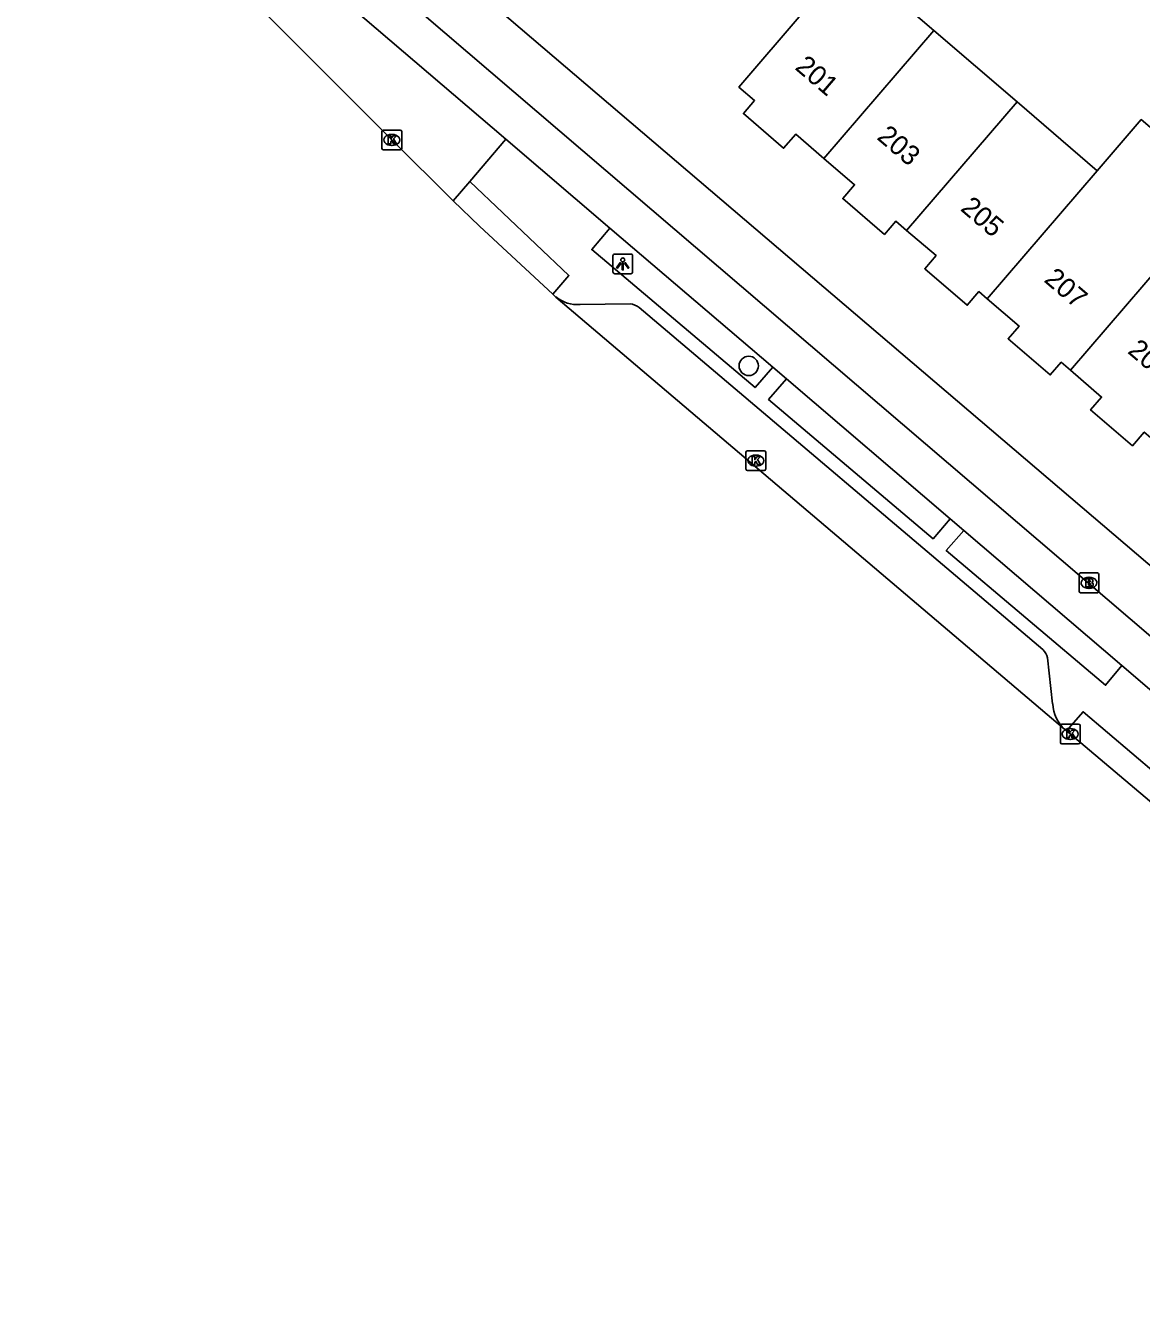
# Model space of a CAD drawing. Extents: x 162532 to 163264, y 381233 to 382042.
# Drawn here: x 162541.7 to 162598.2, y 381729.9 to 381794.9 of the extents above; entities that cross this region are included whole.
import ezdxf

# ---------------------------------------------------------------- set-up
doc = ezdxf.new("R2010")
doc.units = 0
for name, color, linetype in [('IMGEO_Berm_open', 7, 'Continuous'), ('IMGEO_Boom', 7, 'Continuous'), ('IMGEO_Brandkraan', 7, 'Continuous'), ('IMGEO_Fietspad_gesloten', 7, 'Continuous'), ('IMGEO_Kolk', 7, 'Continuous'), ('IMGEO_Lichtpunt', 7, 'Continuous'), ('IMGEO_Pand', 7, 'Continuous'), ('IMGEO_Pand_nummerreeks', 7, 'Continuous'), ('IMGEO_Parkeervlak_open', 7, 'Continuous'), ('IMGEO_Rijbaan_lokaal_gesloten', 7, 'Continuous'), ('IMGEO_Voetpad_open', 7, 'Continuous')]:
    doc.layers.add(name, color=color, linetype=linetype)

msp = doc.modelspace()

# ---------------------------------------------------------------- linework, layer by layer
at = {"layer": 'IMGEO_Berm_open'}
for points in [[(162565.997, 381789.141), (162564.169, 381786.991)], [(162571.272, 381784.63), (162570.345, 381783.548), (162578.617, 381776.558), (162579.513, 381777.583)], [(162580.204, 381776.991), (162579.301, 381775.955), (162587.628, 381768.898), (162588.493, 381769.903)], [(162589.179, 381769.316), (162588.292, 381768.298), (162596.362, 381761.478), (162597.187, 381762.468)]]:
    msp.add_lwpolyline(points, dxfattribs=at)
at = {"layer": 'IMGEO_Boom'}
msp.add_circle((162578.298, 381777.654), 0.489, dxfattribs=at)
at = {"layer": 'IMGEO_Brandkraan'}
for p, q in [((162595.022, 381766.238), (162595.022, 381767.09)), ((162595.097, 381767.164), (162595.949, 381767.164)), ((162595.51, 381766.944), (162595.535, 381766.944)), ((162596.023, 381767.09), (162596.023, 381766.238)), ((162595.949, 381766.164), (162595.097, 381766.164)), ((162595.533, 381766.384), (162595.508, 381766.384))]:
    msp.add_line(p, q, dxfattribs=at)
for points in [[(162595.022, 381766.238), (162595.022, 381767.09)], [(162595.097, 381767.164), (162595.949, 381767.164)], [(162595.37, 381766.864), (162595.37, 381766.464), (162595.583, 381766.464)], [(162595.601, 381766.864), (162595.37, 381766.864)], [(162595.549, 381766.783), (162595.495, 381766.783), (162595.495, 381766.707)], [(162596.023, 381767.09), (162596.023, 381766.238)], [(162595.949, 381766.164), (162595.097, 381766.164)], [(162595.495, 381766.707), (162595.548, 381766.707)], [(162595.557, 381766.631), (162595.495, 381766.631), (162595.495, 381766.55)], [(162595.495, 381766.55), (162595.557, 381766.55)]]:
    msp.add_lwpolyline(points, dxfattribs=at)
for centre, radius, start, end in [((162595.099, 381767.088), 0.0765, 91.55205, 178.44795), ((162595.099, 381767.088), 0.0765, 91.55205, 178.44795), ((162595.55, 381766.745), 0.0379, 267.82845, 90.93552), ((162595.605, 381766.719), 0.145, 59.4692, 91.53667), ((162595.63, 381766.766), 0.0922, 285.51372, 58.15012), ((162595.947, 381767.088), 0.0765, 1.55205, 88.44795), ((162595.947, 381767.088), 0.0765, 1.55205, 88.44795), ((162595.099, 381766.24), 0.0765, 181.55205, 268.44795), ((162595.099, 381766.24), 0.0765, 181.55205, 268.44795), ((162595.558, 381766.59), 0.0404, 269.87594, 90.50774), ((162595.589, 381766.715), 0.251, 268.66757, 293.53466), ((162595.635, 381766.574), 0.105, 301.31148, 78.98903), ((162595.947, 381766.24), 0.0765, 271.55205, 358.44795), ((162595.947, 381766.24), 0.0765, 271.55205, 358.44795)]:
    msp.add_arc(centre, radius, start, end, dxfattribs=at)
for centre, major_axis, ratio, start_param, end_param in [((162595.509, 381766.664), (-0.387, 0.002), 0.722429, 4.712389, 7.853982), ((162595.534, 381766.664), (-0.39, 0.002), 0.717154, 1.570796, 4.712389)]:
    msp.add_ellipse(centre, major_axis=major_axis, ratio=ratio, start_param=start_param, end_param=end_param, dxfattribs=at)
at = {"layer": 'IMGEO_Fietspad_gesloten'}
for points in [[(162680.601, 381693.932), (162634.563, 381733.29), (162601.096, 381761.857), (162549.056, 381806.402), (162548.287, 381807.068)], [(162546.004, 381806.321), (162547.12, 381805.283), (162565.997, 381789.141)], [(162565.997, 381789.141), (162571.272, 381784.63)], [(162571.272, 381784.63), (162579.513, 381777.583)], [(162579.513, 381777.583), (162580.204, 381776.991)], [(162580.204, 381776.991), (162588.493, 381769.903)], [(162588.493, 381769.903), (162589.179, 381769.316)], [(162589.179, 381769.316), (162597.187, 381762.468)], [(162597.187, 381762.468), (162599.877, 381760.168), (162602.123, 381758.248)]]:
    msp.add_lwpolyline(points, dxfattribs=at)
at = {"layer": 'IMGEO_Kolk'}
for p, q in [((162559.801, 381789.6), (162560.653, 381789.6)), ((162559.726, 381788.674), (162559.726, 381789.526)), ((162560.214, 381789.38), (162560.239, 381789.38)), ((162560.727, 381789.526), (162560.727, 381788.674)), ((162560.653, 381788.6), (162559.801, 381788.6)), ((162560.237, 381788.82), (162560.212, 381788.82)), ((162578.153, 381772.431), (162578.153, 381773.283)), ((162578.228, 381773.357), (162579.08, 381773.357)), ((162579.154, 381773.283), (162579.154, 381772.431)), ((162578.641, 381773.137), (162578.666, 381773.137)), ((162579.08, 381772.357), (162578.228, 381772.357)), ((162578.664, 381772.577), (162578.639, 381772.577)), ((162594.072, 381758.581), (162594.072, 381759.433)), ((162594.147, 381759.507), (162594.999, 381759.507)), ((162594.56, 381759.287), (162594.585, 381759.287)), ((162595.073, 381759.433), (162595.073, 381758.581)), ((162594.999, 381758.507), (162594.147, 381758.507)), ((162594.583, 381758.727), (162594.558, 381758.727))]:
    msp.add_line(p, q, dxfattribs=at)
for points in [[(162559.801, 381789.6), (162560.653, 381789.6)], [(162559.726, 381788.674), (162559.726, 381789.526)], [(162560.047, 381789.3), (162560.17, 381789.3), (162560.17, 381789.149), (162560.3, 381789.3), (162560.464, 381789.3), (162560.318, 381789.149), (162560.471, 381788.9), (162560.319, 381788.9), (162560.234, 381789.064), (162560.17, 381788.997), (162560.17, 381788.9), (162560.047, 381788.9), (162560.047, 381789.3)], [(162560.727, 381789.526), (162560.727, 381788.674)], [(162560.653, 381788.6), (162559.801, 381788.6)], [(162578.153, 381772.431), (162578.153, 381773.283)], [(162578.228, 381773.357), (162579.08, 381773.357)], [(162579.154, 381773.283), (162579.154, 381772.431)], [(162578.474, 381773.057), (162578.597, 381773.057), (162578.597, 381772.906), (162578.727, 381773.057), (162578.891, 381773.057), (162578.745, 381772.906), (162578.898, 381772.657), (162578.746, 381772.657), (162578.661, 381772.821), (162578.597, 381772.754), (162578.597, 381772.657), (162578.474, 381772.657), (162578.474, 381773.057)], [(162579.08, 381772.357), (162578.228, 381772.357)], [(162594.072, 381758.581), (162594.072, 381759.433)], [(162594.147, 381759.507), (162594.999, 381759.507)], [(162594.393, 381759.207), (162594.516, 381759.207), (162594.516, 381759.056), (162594.646, 381759.207), (162594.81, 381759.207), (162594.664, 381759.056), (162594.817, 381758.807), (162594.665, 381758.807), (162594.58, 381758.971), (162594.516, 381758.904), (162594.516, 381758.807), (162594.393, 381758.807), (162594.393, 381759.207)], [(162595.073, 381759.433), (162595.073, 381758.581)], [(162594.999, 381758.507), (162594.147, 381758.507)]]:
    msp.add_lwpolyline(points, dxfattribs=at)
for centre, start, end in [((162559.803, 381789.524), 91.55205, 178.44795), ((162559.803, 381789.524), 91.55205, 178.44795), ((162560.651, 381789.524), 1.55205, 88.44795), ((162560.651, 381789.524), 1.55205, 88.44795), ((162559.803, 381788.676), 181.55205, 268.44795), ((162559.803, 381788.676), 181.55205, 268.44795), ((162560.651, 381788.676), 271.55205, 358.44795), ((162560.651, 381788.676), 271.55205, 358.44795), ((162578.23, 381773.281), 91.55205, 178.44795), ((162578.23, 381773.281), 91.55205, 178.44795), ((162579.078, 381773.281), 1.55205, 88.44795), ((162579.078, 381773.281), 1.55205, 88.44795), ((162578.23, 381772.433), 181.55205, 268.44795), ((162578.23, 381772.433), 181.55205, 268.44795), ((162579.078, 381772.433), 271.55205, 358.44795), ((162579.078, 381772.433), 271.55205, 358.44795), ((162594.149, 381759.431), 91.55205, 178.44795), ((162594.149, 381759.431), 91.55205, 178.44795), ((162594.997, 381759.431), 1.55205, 88.44795), ((162594.997, 381759.431), 1.55205, 88.44795), ((162594.149, 381758.583), 181.55205, 268.44795), ((162594.149, 381758.583), 181.55205, 268.44795), ((162594.997, 381758.583), 271.55205, 358.44795), ((162594.997, 381758.583), 271.55205, 358.44795)]:
    msp.add_arc(centre, 0.0765, start, end, dxfattribs=at)
for centre, major_axis, ratio, start_param, end_param in [((162560.213, 381789.1), (-0.387, 0.002), 0.722429, 4.712389, 7.853982), ((162560.238, 381789.1), (-0.39, 0.002), 0.717154, 1.570796, 4.712389), ((162578.64, 381772.857), (-0.387, 0.002), 0.722429, 4.712389, 7.853982), ((162578.665, 381772.857), (-0.39, 0.002), 0.717154, 1.570796, 4.712389), ((162594.559, 381759.007), (-0.387, 0.002), 0.722429, 4.712389, 7.853982), ((162594.584, 381759.007), (-0.39, 0.002), 0.717154, 1.570796, 4.712389)]:
    msp.add_ellipse(centre, major_axis=major_axis, ratio=ratio, start_param=start_param, end_param=end_param, dxfattribs=at)
at = {"layer": 'IMGEO_Lichtpunt'}
for p, q in [((162571.42, 381783.225), (162571.42, 381782.418)), ((162571.42, 381783.225), (162571.42, 381782.418)), ((162572.322, 381783.32), (162571.514, 381783.32)), ((162572.322, 381783.32), (162571.514, 381783.32)), ((162572.416, 381782.418), (162572.416, 381783.225)), ((162572.416, 381782.418), (162572.416, 381783.225)), ((162571.514, 381782.324), (162572.322, 381782.324)), ((162571.514, 381782.324), (162572.322, 381782.324))]:
    msp.add_line(p, q, dxfattribs=at)
for points in [[(162571.794, 381782.889), (162571.833, 381782.861), (162571.645, 381782.599), (162571.607, 381782.626), (162571.794, 381782.889)], [(162571.896, 381782.841), (162571.943, 381782.841), (162571.943, 381782.519), (162571.896, 381782.519), (162571.896, 381782.841)], [(162572.006, 381782.861), (162572.044, 381782.888), (162572.231, 381782.626), (162572.192, 381782.598), (162572.006, 381782.861)]]:
    msp.add_lwpolyline(points, dxfattribs=at)
msp.add_circle((162571.919, 381783.023), 0.0994, dxfattribs=at)
for centre, start, end in [((162571.514, 381783.225), 90, 180), ((162571.514, 381783.225), 90, 180), ((162572.322, 381783.225), 0, 90), ((162572.322, 381783.225), 0, 90), ((162571.514, 381782.418), 180, 270), ((162571.514, 381782.418), 180, 270), ((162572.322, 381782.418), 270, 0), ((162572.322, 381782.418), 270, 360)]:
    msp.add_arc(centre, 0.0946, start, end, dxfattribs=at)
at = {"layer": 'IMGEO_Pand'}
for points in [[(162582.105, 381788.159), (162580.674, 381789.389), (162580.064, 381788.68), (162578.025, 381790.432), (162578.596, 381791.097), (162577.8, 381791.781), (162581.059, 381795.574), (162583.406, 381798.306), (162587.674, 381794.638)], [(162587.674, 381794.638), (162582.105, 381788.159)], [(162587.674, 381794.638), (162591.883, 381791.022)], [(162586.291, 381784.52), (162591.883, 381791.022)], [(162591.883, 381791.022), (162595.939, 381787.536)], [(162595.939, 381787.536), (162598.172, 381790.133), (162602.383, 381786.514)], [(162586.291, 381784.52), (162585.745, 381784.989), (162585.165, 381784.314), (162583.054, 381786.129), (162583.655, 381786.828), (162582.105, 381788.159)], [(162595.939, 381787.536), (162590.368, 381781.056)], [(162602.383, 381786.514), (162600.153, 381783.915), (162594.587, 381777.43)], [(162590.368, 381781.056), (162589.951, 381781.415), (162589.36, 381780.727), (162587.209, 381782.576), (162587.78, 381783.24), (162586.291, 381784.52)], [(162594.587, 381777.43), (162594.114, 381777.836), (162593.561, 381777.193), (162591.426, 381779.027), (162591.98, 381779.671), (162590.368, 381781.056)], [(162598.952, 381773.754), (162598.317, 381774.3), (162597.722, 381773.608), (162595.606, 381775.427), (162596.163, 381776.075), (162594.587, 381777.43)]]:
    msp.add_lwpolyline(points, dxfattribs=at)
at = {"layer": 'IMGEO_Parkeervlak_open'}
for points in [[(162572.288, 381780.793), (162569.763, 381780.76)], [(162593.185, 381763.279), (162572.745, 381780.619)], [(162593.683, 381760.532), (162593.426, 381762.861)]]:
    msp.add_lwpolyline(points, dxfattribs=at)
for centre, radius, start, end in [((162569.647, 381782.557), 1.8, 231.73752, 273.6976), ((162572.202, 381779.879), 0.918, 53.70414, 84.6078), ((162592.627, 381762.679), 0.819, 12.83391, 47.09772), ((162595.587, 381760.647), 1.907, 183.45402, 227.45198)]:
    msp.add_arc(centre, radius, start, end, dxfattribs=at)
at = {"layer": 'IMGEO_Rijbaan_lokaal_gesloten'}
for points in [[(162563.333, 381786.008), (162560.227, 381789.1), (162552.821, 381796.54), (162541.866, 381807.508), (162541.691, 381807.666)], [(162568.384, 381781.28), (162564.665, 381784.731), (162563.333, 381786.008)], [(162568.532, 381781.143), (162568.384, 381781.28)], [(162594.297, 381759.242), (162568.532, 381781.143)], [(162594.384, 381759.168), (162594.297, 381759.242)], [(162599.342, 381754.973), (162594.573, 381759.007), (162594.384, 381759.168)]]:
    msp.add_lwpolyline(points, dxfattribs=at)
at = {"layer": 'IMGEO_Voetpad_open'}
for points in [[(162549.054, 381809.864), (162602.511, 381764.218)], [(162564.169, 381786.991), (162563.333, 381786.008)], [(162568.384, 381781.28), (162569.192, 381782.231), (162564.169, 381786.991)], [(162599.342, 381754.973), (162600.155, 381755.935), (162595.221, 381760.134), (162594.384, 381759.168)]]:
    msp.add_lwpolyline(points, dxfattribs=at)

# ---------------------------------------------------------------- texts
at = {"layer": 'IMGEO_Pand_nummerreeks'}
for s, rotation, p in [('201', 319.52102, (162580.589, 381792.713)), ('203', 319.52102, (162584.735, 381789.175)), ('205', 319.52102, (162588.967, 381785.563)), ('207', 319.52053, (162593.198, 381781.952)), ('209', 319.52053, (162597.43, 381778.34))]:
    msp.add_text(s, height=1, rotation=rotation, dxfattribs=at).set_placement(p)

doc.saveas('drawing.dxf')
